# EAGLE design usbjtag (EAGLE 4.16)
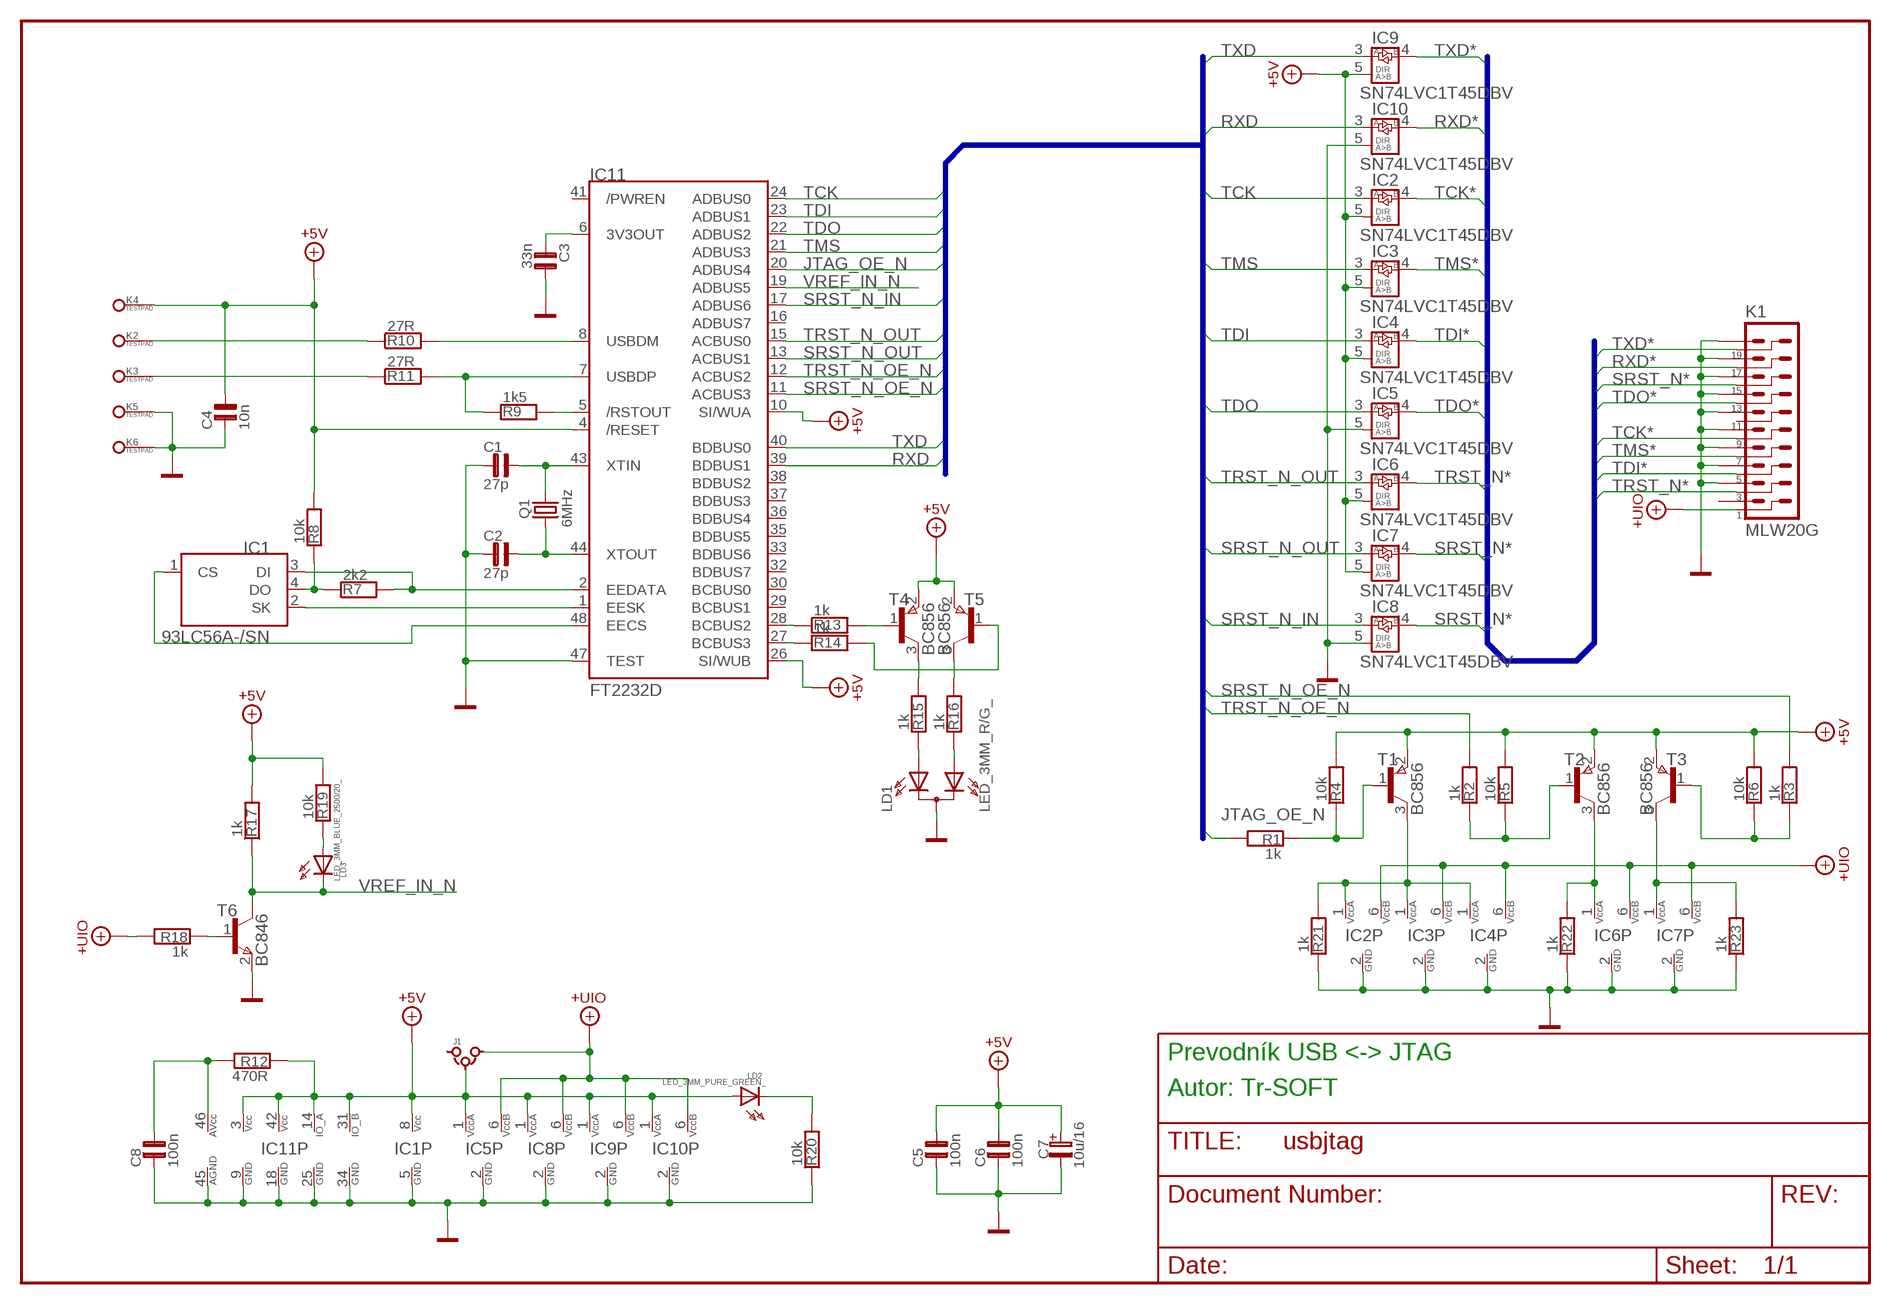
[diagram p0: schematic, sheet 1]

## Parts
C1  27p  C0805  [C0805]
C2  27p  C0805  [C0805]
C3  33n  C0805  [C0805]
C4  10n  C0805  [C0805]
C5  100n  C0805  [C0805]
C6  100n  C0805  [C0805]
C7  10u/16  CTANSMD-A  [CTANSMD-A]
C8  100n  C0805  [C0805]
IC1  93LC56A-/SN  [SO8]
IC2  SN74LVC1T45DBV  [SOT23-6]
IC3  SN74LVC1T45DBV  [SOT23-6]
IC4  SN74LVC1T45DBV  [SOT23-6]
IC5  SN74LVC1T45DBV  [SOT23-6]
IC6  SN74LVC1T45DBV  [SOT23-6]
IC7  SN74LVC1T45DBV  [SOT23-6]
IC8  SN74LVC1T45DBV  [SOT23-6]
IC9  SN74LVC1T45DBV  [SOT23-6]
IC10  SN74LVC1T45DBV  [SOT23-6]
IC11  FT2232D  [LQFP48]
J1  JUMPER_3  [S1G03J]
K1  MLW20G  MLW20G_  [MLW20G_]
K2  TESTPAD  [TESTPAD]
K3  TESTPAD  [TESTPAD]
K4  TESTPAD  [TESTPAD]
K5  TESTPAD  [TESTPAD]
K6  TESTPAD  [TESTPAD]
LD1  LED_3MM_R/G_  [LED_3MM_DUO_SMD]
LD2  LED_3MM_PURE_GREEN_  [LED_3MM_SMD]
LD3  LED_3MM_BLUE_2500/20_  [LED_3MM_SMD]
Q1  6MHz  Q-HC49/S  [Q-HC49/S]
R1  1k  R0805  [R0805]
R2  1k  R0805  [R0805]
R3  1k  R0805  [R0805]
R4  10k  R1206  [R1206]
R5  10k  R0805  [R0805]
R6  10k  R0805  [R0805]
R7  2k2  R0805  [R0805]
R8  10k  R0805  [R0805]
R9  1k5  R1206  [R1206]
R10  27R  R0805  [R0805]
R11  27R  R0805  [R0805]
R12  470R  R0805  [R0805]
R13  1k  R0805  [R0805]
R14  1k  R0805  [R0805]
R15  1k  R0805  [R0805]
R16  1k  R0805  [R0805]
R17  1k  R1206  [R1206]
R18  1k  R0805  [R0805]
R19  10k  R0805  [R0805]
R20  10k  R0805  [R0805]
R21  1k  R0805  [R0805]
R22  1k  R0805  [R0805]
R23  1k  R0805  [R0805]
T1  BC856  [SOT23]
T2  BC856  [SOT23]
T3  BC856  [SOT23]
T4  BC856  [SOT23]
T5  BC856  [SOT23]
T6  BC846  [SOT23]

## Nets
+5V: C4.2 C5.2 C6.2 C7.1(+) IC1.8(VCC) IC2.5(DIR) IC3.5(DIR) IC4.5(DIR) IC5.1(VCCA) IC6.5(DIR) IC7.5(DIR) IC8.1(VCCA) IC9.1(VCCA) IC9.5(DIR) IC10.1(VCCA) IC11.3(VCC) IC11.4(/RESET) IC11.10(SI/WUA) IC11.14(VCCIOA) IC11.26(SI/WUB) IC11.31(VCCIOB) IC11.42(VCC) J1.2(C) K4.1(P) LD2.A R4.2 R5.2 R6.2 R8.2 R12.1 R17.2 R19.2 T1.2(E) T2.2(E) T3.2(E) T4.2(E) T5.2(E)
+UIO: IC2.6(VCCB) IC3.6(VCCB) IC4.6(VCCB) IC5.6(VCCB) IC6.6(VCCB) IC7.6(VCCB) IC8.6(VCCB) IC9.6(VCCB) IC10.6(VCCB) J1.3 K1.1 R18.2
AVCC: C8.2 IC11.46(AVCC) R12.2
GND: C1.1 C2.1 C3.2 C4.1 C5.1 C6.1 C7.2(-) C8.1 IC1.5(GND) IC2.2(GND) IC3.2(GND) IC4.2(GND) IC5.2(GND) IC5.5(DIR) IC6.2(GND) IC7.2(GND) IC8.2(GND) IC8.5(DIR) IC9.2(GND) IC10.2(GND) IC10.5(DIR) IC11.9(GND) IC11.18(GND) IC11.25(GND) IC11.34(GND) IC11.45(AGND) IC11.47(TEST) K1.4 K1.6 K1.8 K1.10 K1.12 K1.14 K1.16 K1.18 K1.20 K5.1(P) K6.1(P) LD1.C(K) R20.1 R21.1 R22.1 R23.1 T6.2(E)
JTAG_OE: IC2.1(VCCA) IC3.1(VCCA) IC4.1(VCCA) R21.2 T1.3(C)
JTAG_OE_N: IC11.20(ADBUS4) R1.2
N$1: R1.1 R4.1 T1.1(B)
N$2: IC1.1(CS) IC11.48(EECS)
N$3: LD3.A R19.1
N$4: R18.1 T6.1(B)
N$5: IC1.2(SK) IC11.1(EESK)
N$6: R2.1 R5.1 T2.1(B)
N$7: R3.1 R6.1 T3.1(B)
N$8: IC1.3(DI) IC11.2(EEDATA) R7.2
N$9: IC1.4(DO) R7.1 R8.1
N$10: C1.2 IC11.43(XTIN) Q1.2
N$11: C2.2 IC11.44(XTOUT) Q1.1
N$12: LD2.C(K) R20.2
N$13: C3.1 IC11.6(3V3OUT)
N$14: IC11.5(/RSTOUT) R9.2
N$19: R15.2 T4.3(C)
N$20: R16.2 T5.3(C)
N$21: LD1.A2(AR) R15.1
N$22: LD1.A1(AG) R16.1
N$24: R13.2 T4.1(B)
N$25: R14.2 T5.1(B)
N$26: IC11.28(BCBUS2) R13.1
N$27: IC11.27(BCBUS3) R14.1
RXD: IC10.3(A) IC11.39(BDBUS1)
RXD*: IC10.4(B) K1.17
SRST_N*: IC7.4(B) IC8.4(B) K1.15
SRST_N_IN: IC8.3(A) IC11.17(ADBUS6)
SRST_N_OE_N: IC11.11(ACBUS3) R3.2
SRST_N_OUT: IC7.3(A) IC11.13(ACBUS1)
TCK: IC2.3(A) IC11.24(ADBUS0)
TCK*: IC2.4(B) K1.9
TDI: IC4.3(A) IC11.23(ADBUS1)
TDI*: IC4.4(B) K1.5
TDO: IC5.3(A) IC11.22(ADBUS2)
TDO*: IC5.4(B) K1.13
TMS: IC3.3(A) IC11.21(ADBUS3)
TMS*: IC3.4(B) K1.7
TRST_N*: IC6.4(B) K1.3
TRST_N_OE_N: IC11.12(ACBUS2) R2.2
TRST_N_OUT: IC6.3(A) IC11.15(ACBUS0)
TXD: IC9.3(A) IC11.40(BDBUS0)
TXD*: IC9.4(B) K1.19
USBDM: IC11.8(USBDM) R10.2
USBDM*: K2.1(P) R10.1
USBDP: IC11.7(USBDP) R9.1 R11.2
USBDP*: K3.1(P) R11.1
VCC_SRST: IC7.1(VCCA) R23.2 T3.3(C)
VCC_TRST: IC6.1(VCCA) R22.2 T2.3(C)
VREF_IN_N: IC11.19(ADBUS5) LD3.C(K) R17.1 T6.3(C)
Unconnected: IC11.16(ADBUS7) IC11.29(BCBUS1) IC11.30(BCBUS0) IC11.32(BDBUS7) IC11.33(BDBUS6) IC11.35(BDBUS5) IC11.36(BDBUS4) IC11.37(BDBUS3) IC11.38(BDBUS2) IC11.41(/PWREN) J1.1 K1.2 K1.11

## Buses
TRST_N*,TDI*,TMS*,TCK*,TDO*,SRST_N*,RXD*,TXD*
TCK,TMS,TDI,TDO,JTAG_OE_N,TRST_N_OE_N,TRST_N_OUT,SRST_N_OE_N,SRST_N_OUT,SRST_N_IN,RXD,TXD

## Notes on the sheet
- Prevodník USB <-> JTAG
- Autor: Tr-SOFT

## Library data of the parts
C1-C6 C8 = PASSIVE:C
C7 = PASSIVE:CTANSMD
IC1 = IO:93*56A-/?: Microwire 2kb ( 256B x 8 ) Serial EEPROM
IC2-IC10 = TTL74:SN74LVC1T45*
IC11 = IO:FT2232D
J1 = connectors:JUMPER_3
K1 = connectors:MLW20
K2-K6 = connectors:TESTPAD
LD1 = ACTIVE:LED_3MM_R/G
LD2 LD3 = ACTIVE:LED_3MM_*: Circle LED 3mm diamater.
Q1 = PASSIVE:Q-HC49
R1-R23 = PASSIVE:R
T1-T5 = ACTIVE:BC856
T6 = ACTIVE:BC846

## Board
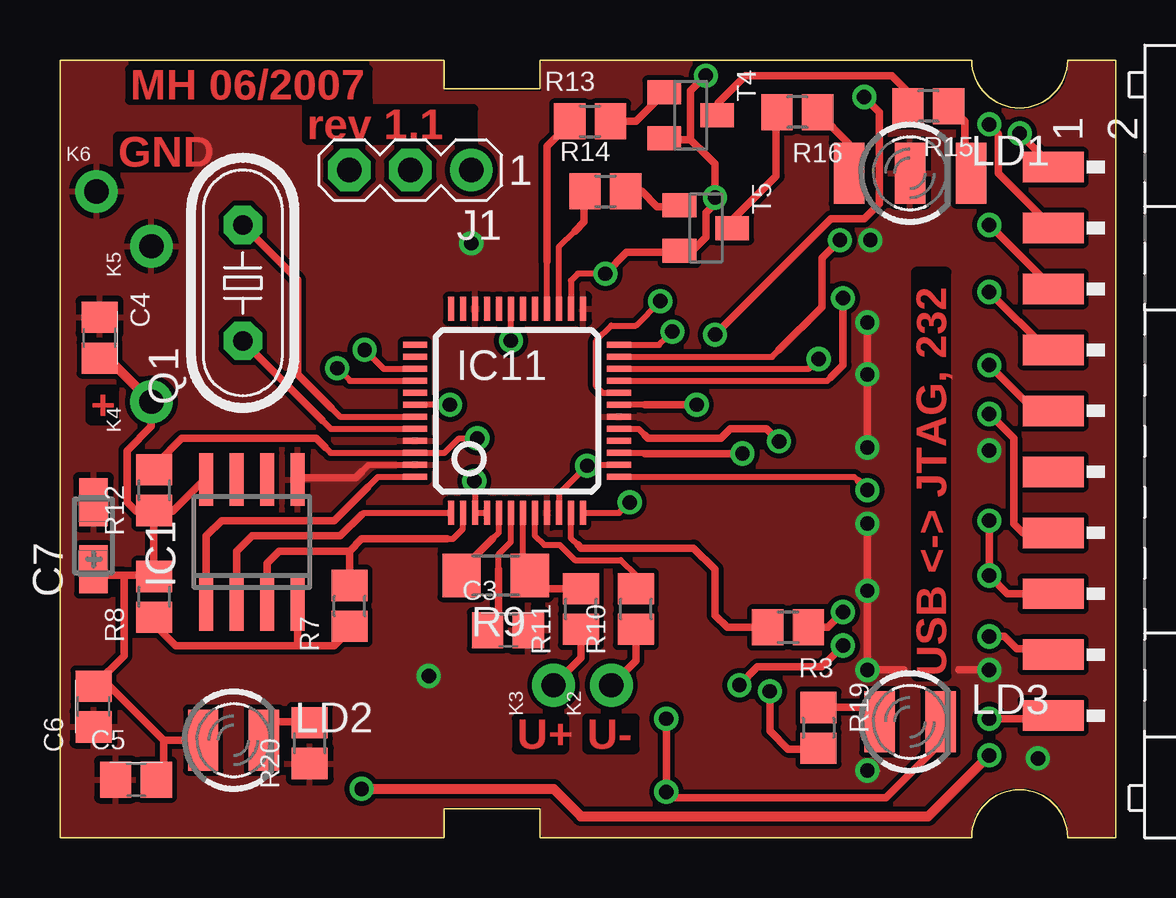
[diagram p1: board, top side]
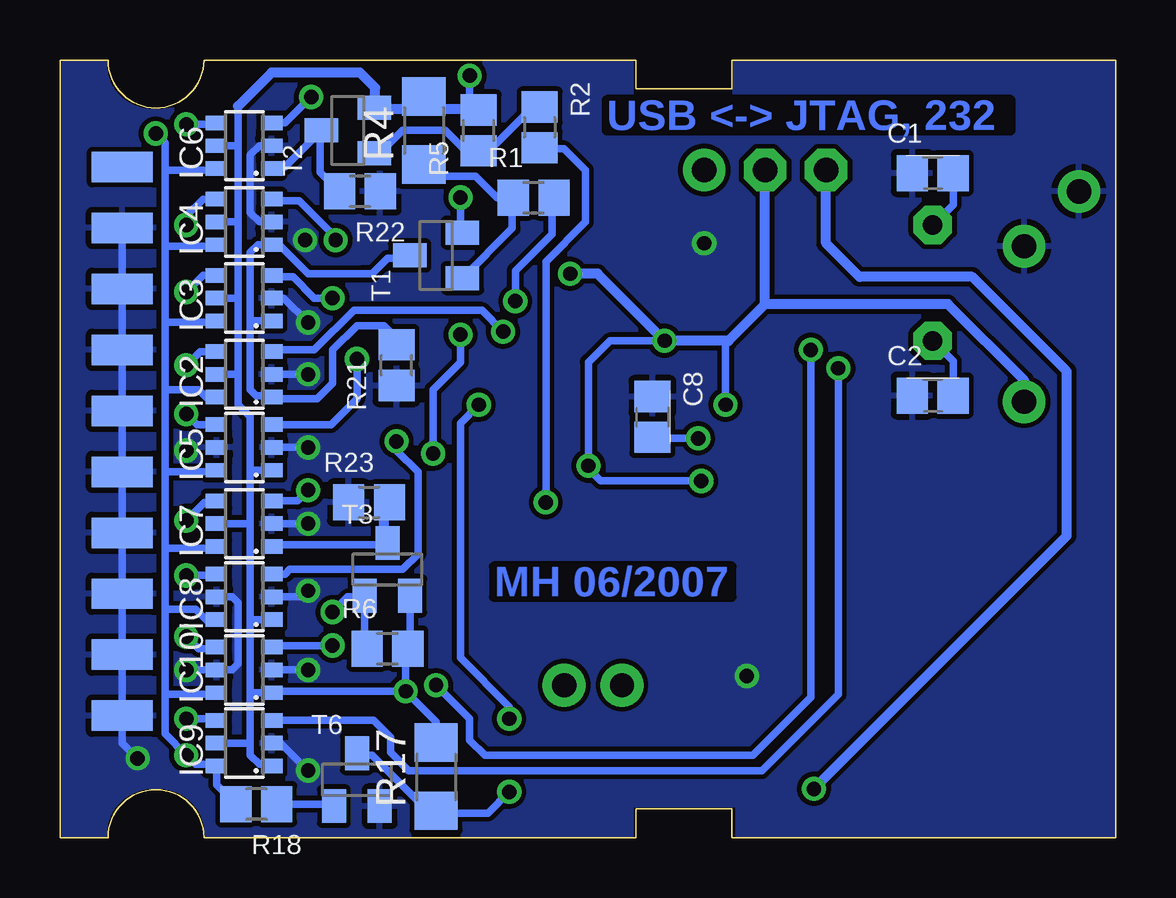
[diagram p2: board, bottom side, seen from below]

Size 44 x 32.4 mm. Coordinates in mm from the lower left corner, seen from the top.
Outline: 0,0 0,32.4 16,32.4 16,31.2 20,31.2 20,32.4 38,32.4 arc180 42,32.4 44,32.4 44,0 42,0 arc180 38,0 20,0 20,1.2 16,1.2 16,0 0,0
Copper layers (1*16): Top 0.035mm / dielectric 1.5mm / Bottom 0.035mm
Design rules "default": minimum track width 10mil, minimum drill 23mil, track to track 8mil, track to pad 8mil, pad to pad 8mil, via to via 8mil, smd to smd 8mil, copper to edge 0mil, drill to drill 8mil, minimum pad ring 10mil, minimum via ring 8mil, stop-mask expansion 4mil, vias tented up to drill 24mil, thermal gap 10mil

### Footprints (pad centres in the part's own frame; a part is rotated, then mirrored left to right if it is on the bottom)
C0805 = smd 1.3 x 1.5: 1 -0.85,0; 2 0.85,0
CTANSMD-A = smd 2 x 1.2: 1 -1.4,0; 2 1.4,0
SO8 = smd 0.6 x 2.2: 1 -1.905,-2.6; 2 -0.635,-2.6; 3 0.635,-2.6; 4 1.905,-2.6; 5 1.905,2.6; 6 0.635,2.6; 7 -0.635,2.6; 8 -1.905,2.6
SOT23-6 = smd 0.6 x 0.9: 1 -0.95,-1.15; 2 0,-1.15; 3 0.95,-1.15; 4 0.95,1.15; 5 0,1.15; 6 -0.95,1.15
LQFP48 = smd 0.26 x 1: 1 -2.75,-4.25; 2 -2.25,-4.25; 3 -1.75,-4.25; 4 -1.25,-4.25; 5 -0.75,-4.25; 6 -0.25,-4.25; 7 0.25,-4.25; 8 0.75,-4.25; 9 1.25,-4.25; 10 1.75,-4.25; 11 2.25,-4.25; 12 2.75,-4.25; 25 2.75,4.25; 26 2.25,4.25; 27 1.75,4.25; 28 1.25,4.25; 29 0.75,4.25; 30 0.25,4.25; 31 -0.25,4.25; 32 -0.75,4.25; 33 -1.25,4.25; 34 -1.75,4.25; 35 -2.25,4.25; 36 -2.75,4.25 | smd 1 x 0.26: 13 4.25,-2.75; 14 4.25,-2.25; 15 4.25,-1.75; 16 4.25,-1.25; 17 4.25,-0.75; 18 4.25,-0.25; 19 4.25,0.25; 20 4.25,0.75; 21 4.25,1.25; 22 4.25,1.75; 23 4.25,2.25; 24 4.25,2.75; 37 -4.25,2.75; 38 -4.25,2.25; 39 -4.25,1.75; 40 -4.25,1.25; 41 -4.25,0.75; 42 -4.25,0.25; 43 -4.25,-0.25; 44 -4.25,-0.75; 45 -4.25,-1.25; 46 -4.25,-1.75; 47 -4.25,-2.25; 48 -4.25,-2.75
S1G03J = drill 1.016 pad 1.778 round: 1 -2.54,0 | drill 1.016 pad 1.778 octagon: 2 0,0; 3 2.54,0
MLW20G_ = smd 1.27 x 2.54: 1 -11.43,-0.508; 3 -8.89,-0.508; 5 -6.35,-0.508; 7 -3.81,-0.508; 9 -1.27,-0.508; 11 1.27,-0.508; 13 3.81,-0.508; 15 6.35,-0.508; 17 8.89,-0.508; 19 11.43,-0.508 | smd 1.27 x 2.54 bottom: 2 -11.43,-0.508; 4 -8.89,-0.508; 6 -6.35,-0.508; 8 -3.81,-0.508; 10 -1.27,-0.508; 12 1.27,-0.508; 14 3.81,-0.508; 16 6.35,-0.508; 18 8.89,-0.508; 20 11.43,-0.508
TESTPAD = drill 1.016 pad 1.778 round: 1 0,0
LED_3MM_DUO_SMD = smd 1.27 x 2.54: A1 -2.54,0; A2 2.54,0; C 0,0
LED_3MM_SMD = smd 1.27 x 2.54: A -1.27,0; C 1.27,0
Q-HC49/S = drill 0.813 pad 1.6 octagon: 1 -2.413,0; 2 2.413,0
R0805 = smd 1.3 x 1.5: 1 -0.85,0; 2 0.85,0
R1206 = smd 1.6 x 1.803: 1 -1.422,0; 2 1.422,0
SOT23 = smd 1 x 1.4: 1 -0.95,-1.1; 2 0.95,-1.1; 3 0,1.1

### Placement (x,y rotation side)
C1  7.62,27.69 0 bottom
C2  7.62,18.41 0 bottom
C3  18.67,8.64 0 top
C4  1.65,20.83 270 top
C5  3.17,2.41 0 top
C6  1.4,5.46 90 top
C7  1.4,12.57 90 top
C8  19.3,17.53 270 bottom
IC1  8,12.32 0 top
IC2  36.32,19.3 90 bottom
IC3  36.32,22.48 90 bottom
IC4  36.32,25.65 90 bottom
IC5  36.32,16.26 90 bottom
IC6  36.32,28.83 90 bottom
IC7  36.32,13.08 90 bottom
IC8  36.32,10.03 90 bottom
IC9  36.32,3.94 90 bottom
IC10  36.32,6.99 90 bottom
IC11  19.05,17.78 0 top
J1  14.61,27.81 180 top
K1  41.91,16.51 270 top
K2  22.99,6.35 90 top
K3  20.57,6.35 90 top
K4  3.81,18.16 90 top
K5  3.81,24.64 90 top
K6  1.52,26.92 0 top
LD1  35.43,27.69 0 top
LD2  7.24,4.06 0 top
LD3  35.43,4.83 0 top
Q1  7.62,23.11 90 top
R1  24.26,26.67 0 bottom
R2  24,29.59 270 bottom
R3  30.35,8.76 180 top
R4  28.83,29.46 90 bottom
R5  26.54,29.46 90 bottom
R6  30.35,7.87 0 bottom
R7  12.06,9.65 90 top
R8  3.94,10.03 90 top
R9  18.16,10.92 180 top
R10  24,9.53 90 top
R11  21.72,9.53 90 top
R12  3.94,14.48 90 top
R13  22.1,29.84 0 top
R14  22.73,26.92 0 top
R15  36.2,30.48 180 top
R16  30.73,30.23 180 top
R17  28.32,2.54 90 bottom
R18  35.81,1.4 180 bottom
R19  31.62,4.57 270 top
R20  10.41,3.94 90 top
R21  29.97,19.68 90 bottom
R22  31.5,26.92 180 bottom
R23  31.11,13.97 0 bottom
T1  28.32,24.26 90 bottom
T2  32,29.46 90 bottom
T3  30.35,11.18 0 bottom
T4  26.29,30.1 270 top
T5  26.92,25.4 270 top
T6  31.62,2.41 0 bottom

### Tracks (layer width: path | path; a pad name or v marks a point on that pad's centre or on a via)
+5V  (via drill 0.6)
  Top 0.254: IC11.4 17.79,13.53 17.78,13.53 IC11.3 17.3,14.83 v17.27,14.86 | 18.8,20.83 IC11.31 | IC11.14 22.01,15.53 v21.97,15.49 20.8,14.32 IC11.10 | IC11.42 v16.25,18.03 v16.26,18.03 | IC11.26 21.3,23.2 21.59,23.5 v22.73,23.5
  Top 0.303: v29.59,6.1 29.59,4.45 30.35,3.68 31.62,3.68 R19.2 | 6.1,14.99 IC1.8 | 6.1,14.99 6.01,14.99 | 6.1,14.99 4.7,13.59 3.94,13.59 | K4.1 3.81,17.14 2.79,16.13 2.79,13.97 3.17,13.59 3.94,13.59 | 4.32,4.06 LD2.A | 4.32,4.06 2.03,6.35 1.44,6.35 | 1.44,6.35 C6.2 | C5.2 4.32,2.71 4.32,4.06 | v22.73,23.5 23.62,24.38 25.78,24.38 25.82,24.43 T5.2 26.36,24.45 26.92,25.02 | C7.1 1.4,10.92 2.67,10.92 | 3.9,10.92 R8.2 | 2.67,10.92 3.9,10.92 | 1.44,6.35 2.67,7.58 2.67,10.92 | v26.92,31.75 26.29,31.11 26.29,29.08 | T4.2 25.25,29.08 26.29,29.08 | 26.92,28.45 26.29,29.08 | 3.94,13.59 R12.1 | 3.9,10.92 3.9,13.55 3.94,13.59 | 18.8,20.83 v18.8,20.7
  Top 0.305: 26.92,25.02 26.92,26.04 27.3,26.42 v27.3,26.67 27.3,28.07 26.92,28.45
  Top 0.406: C4.2 1.99,19.98 K4.1
  Bottom 0.303: 36.58,28.83 IC6.5 | 36.58,22.48 36.58,19.3 | 36.58,25.65 36.58,22.48 | 36.58,28.83 36.58,25.65 | 36.58,25.65 IC4.5 | 36.58,22.48 IC3.5 | 36.58,19.3 IC2.5 | 36.58,19.3 36.58,18.03 36.07,17.53 36.07,15.37 | 36.07,15.37 36.07,13.08 | 36.07,3.94 36.07,3.43 35.69,3.05 35.18,3.05 35.17,3.04 IC9.1 | 36.07,6.1 36.07,3.94 | 36.07,9.14 36.07,6.1 | 36.07,13.08 36.07,9.14 | 36.07,3.94 IC9.5 | 36.07,6.1 36.01,6.04 IC10.1 35.18,6.1 v29.59,6.1 | IC8.1 36.01,9.08 36.07,9.14 | 36.07,13.08 IC7.5 | IC5.1 36.01,15.31 36.07,15.37 | 36.58,30.48 36.58,28.83 | R5.2 26.84,30.31 | 29.59,7.87 R6.2 | T3.2 29.4,8.06 29.59,7.87 | R5.2 26.54,30.35 | v29.59,6.1 29.59,7.87 | R17.2 28.32,4.83 v29.59,6.1 | v17.27,14.86 21.46,14.86 21.97,15.37 v21.97,15.49 21.97,19.81 21.08,20.7 v18.8,20.7 | v16.26,18.03 v16.25,18.04 16.26,18.04 16.26,20.7 | R5.2 26.58,30.35 26.92,30.35 v26.92,31.75
  Bottom 0.305: T1.2 27.3,25.29 v27.3,26.67
  Bottom 0.406: 36.58,30.48 35.18,31.88 31.5,31.88 30.86,31.24 30.86,30.35 | v22.73,23.5 21.59,23.5 v18.8,20.7 16.26,20.7 16.13,20.7 14.61,22.23 | K4.1 3.81,19.05 6.99,22.23 14.61,22.23 | 14.61,22.23 J1.2 | 30.96,30.35 30.99,30.35 | 30.96,30.35 T2.2 30.86,30.37 30.86,30.35 | 30.86,30.35 29.36,30.35 R4.2 28.83,30.35 26.54,30.35 | 30.86,30.35 30.96,30.35
+UIO  (via drill 0.6)
  Top 0.303: v40.01,29.34 K1.1
  Top 0.406: v38.73,3.43 36.2,0.89 21.72,0.89 20.57,2.03 v12.57,2.03
  Bottom 0.303: 39.62,24.64 39.62,27.81 | 39.62,21.46 39.62,24.64 | 39.62,18.67 39.62,21.46 | 39.62,15.24 39.62,18.67 | 39.62,12.06 39.62,15.24 | 39.62,5.97 39.62,4.32 v38.73,3.43 38.35,3.05 37.47,3.05 37.47,3.04 IC9.6 37.47,2.2 R18.2 | 39.62,5.97 39.62,9.53 | 39.62,9.53 39.62,12.06 | IC4.6 37.54,24.64 39.62,24.64 | IC3.6 37.54,21.46 39.62,21.46 | IC2.6 37.54,18.29 37.85,18.29 38.23,18.67 39.62,18.67 | IC5.6 37.54,15.24 39.62,15.24 | IC7.6 37.54,12.06 39.62,12.06 | IC8.6 37.54,9.02 37.85,9.02 38.35,9.53 39.62,9.53 | IC10.6 37.54,5.97 39.62,5.97 | v40.01,29.34 39.62,28.96 39.62,27.81 | IC6.6 37.54,27.81 39.62,27.81
  Bottom 0.406: v12.57,2.03 2.03,12.57 2.03,19.43 5.97,23.37 10.67,23.37 12.06,24.77 J1.3
AVCC  (via drill 0.6)
  Top 0.254: 11.05,16.26 11.28,16.03 IC11.46 16.03,16.03 16.64,16.64 v17.4,16.64
  Top 0.303: 11.05,16.26 10.67,16.64 5.08,16.64 4.06,15.62 4.06,15.37 3.98,15.37 R12.2
  Bottom 0.303: C8.2 19.3,16.64 v17.4,16.64
GND  (via drill 0.6)
  Top 0.254: IC11.47 12.86,15.53 12.57,15.24
  Top 0.303: v33.66,13.08 v33.66,10.29 v33.66,6.99 IC10.2 | v33.66,16.26 v33.66,19.3 v33.66,21.46 | v33.66,2.79 34.04,2.79 | v38.73,6.99 IC10.5 | 12.57,15.24 12.32,14.99 9.91,14.99 IC1.5
  Bottom 0.303: IC4.2 35.69,25.65 36.07,26.04 36.07,28.45 35.69,28.83 IC6.2 | IC8.5 36.83,10.03 36.58,9.78 36.58,7.24 36.83,6.99 IC10.5 | IC10.5 | v33.66,21.46 34.67,22.48 IC3.2 | v33.66,19.3 IC2.2 | IC5.2 v33.66,16.26 | v33.66,13.08 IC7.2 | v33.66,10.29 33.91,10.03 IC8.2 | IC10.2 v33.66,6.99 | IC9.2 34.8,3.94 v33.66,2.79 | IC10.5 v38.73,6.99 | K1.4 K1.6 K1.8 K1.10 K1.12 K1.14 K1.16 K1.18 K1.20 41.4,3.94 v40.77,3.3
  other vias: 33.78,24.89 38.73,16.13 15.37,6.73 17.14,24.77
  pour Top: 0.25,32.26 15.88,32.26 15.88,30.99 20.19,30.99 20.19,32.26 37.85,32.26 arc90 39.88,30.23 40.01,30.23 40.13,30.23 arc90 42.16,32.26 43.81,32.26 43.81,29.97 43.81,26.8 43.81,19.81 43.81,15.11 43.81,8.13 43.81,0.13 42.16,0.13 arc90 40.13,2.16 40.01,2.16 39.88,2.16 arc90 37.85,0.13 20.19,0.13 20.19,1.4 15.88,1.4 15.88,0.13 0.13,0.13 0.13,3.3 0.13,9.53 0.13,17.14 0.13,25.53 0.13,32.26
  pour Bottom: 0.13,32.26 15.88,32.26 15.88,30.99 20.19,30.99 20.19,32.26 37.72,32.26 37.85,32.26 arc90 39.88,30.23 40.01,30.23 40.13,30.23 arc90 42.16,32.26 43.81,32.26 43.81,26.16 43.81,16.38 43.81,10.29 43.81,0.13 42.16,0.13 arc90 40.13,2.16 40.01,2.16 39.88,2.16 arc90 37.85,0.13 20.19,0.13 20.19,1.4 15.75,1.4 15.75,0.13 0.13,0.13 0.13,8.26 0.13,20.95
JTAG_OE
  Bottom 0.303: 36.07,21.59 36.07,18.67 35.81,18.41 35.18,18.41 35.17,18.41 IC2.1 | 36.07,21.59 36.07,24.38 35.75,24.7 IC4.1 35.17,24.64 35.18,24.64 34.8,24.64 33.66,23.5 31.37,23.5 | IC3.1 36.01,21.53 36.07,21.59
  Bottom 0.305: T1.3 29.55,24.13 30.35,24.13 30.99,23.5 31.37,23.5 | R21.2 29.97,20.83 30.48,21.34 31.62,21.34 32.64,20.32 32.64,18.92 33.27,18.29 35.18,18.29 35.17,18.3 IC2.1
JTAG_OE_N  (via drill 0.6)
  Top 0.254: IC11.20 22.62,18.53 22.35,18.8 22.35,20.7 22.99,21.34 24,21.34 v25.02,22.35
  Bottom 0.305: v25.02,22.35 25.02,23.62 23.5,25.15 23.5,26.67 R1.2
N$1
  Bottom 0.305: 25.15,26.67 25.78,26.67 26.67,27.56 28.32,27.56 28.83,28.07 R4.1 | 25.15,26.67 R1.1 | T1.1 25.15,25.38 25.15,26.67
N$2
  Top 0.254: IC11.48 13.25,15.03 12.83,14.61
  Top 0.303: IC1.1 6.1,12.57 6.73,13.21 11.43,13.21 12.83,14.61
N$3
  Top 0.303: LD3.A 34.16,5.21 33.95,5.42 R19.1
N$4
  Bottom 0.303: T6.1 32.51,1.37 32.51,1.4 R18.1
N$5
  Top 0.254: IC11.1 12.64,13.53 12.57,13.46
  Top 0.303: IC1.2 7.37,11.94 8,12.57 11.68,12.57 12.57,13.46
N$6
  Bottom 0.303: 30.97,28.45 30.99,28.45 | 30.97,28.45 T2.1 | 30.97,28.45 30.73,28.45 29.72,29.46 27.94,29.46
  Bottom 0.305: 27.94,29.46 27.05,28.57 26.54,28.57 R5.1 26.54,28.7 26.04,28.7 24.26,30.48 24,30.48 R2.1
N$7  (via drill 0.6)
  Top 0.303: R3.1 31.24,8.8 31.24,8.76 32,8.76 v32.64,9.4
  Bottom 0.303: R6.1 31.24,7.87 31.3,7.93 | 31.3,7.93 T3.1 31.26,10.03 | 31.3,7.93 31.36,7.87 | 31.26,10.03 31.24,10.03 | v32.64,9.4 32,10.03 31.26,10.03
N$8
  Top 0.254: 16.13,12.45 16.38,12.45 16.8,12.86 IC11.2
  Top 0.303: 12.06,11.94 9.14,11.94 8.64,11.43 IC1.3 | 12.06,11.94 12.57,12.45 16.13,12.45 | 12.06,11.94 R7.2
N$9
  Top 0.303: 9.91,8 4.83,8 3.94,8.89 R8.1 | 9.91,8 11.43,8 12.06,8.64 R7.1 | 9.91,8 IC1.4
N$10
  Top 0.254: IC11.43 11.68,17.53 11.3,17.91
  Top 0.303: 11.3,17.91 9.91,19.3 9.91,23.24 Q1.2
  Bottom 0.303: C1.2 6.77,26.38 Q1.2
N$11
  Top 0.254: IC11.44 11.29,17.03 10.92,17.4
  Top 0.303: Q1.1 8.47,19.85 10.92,17.4
  Bottom 0.303: C2.2 6.77,19.85 Q1.1
N$12
  Top 0.303: R20.2 10.41,4.83 8.51,4.83 LD2.C
N$13
  Top 0.254: IC11.6 18.8,12.32 18.29,11.81 18.29,11.18
  Top 0.303: 18.29,11.18 18.29,9.14 17.91,8.76 17.78,8.76 17.78,8.68 C3.1
N$14
  Top 0.254: IC11.5 18.3,12.71 18.03,12.45
  Top 0.303: R9.2 16.74,11.15 18.03,12.45
N$19
  Top 0.303: R15.2 35.31,30.48 35.31,31.11 34.67,31.75 28.57,31.75 27.43,30.61 27.43,30.1 T4.3
N$20
  Top 0.303: T5.3 28.07,25.4 28.02,25.44 | 29.84,30.23 R16.2
  Top 0.305: 29.84,30.23 29.84,27.56 28.07,25.78 28.07,25.44 T5.3
N$21
  Top 0.303: R15.1 37.08,30.48 37.72,29.84 37.72,27.69 LD1.A2
N$22
  Top 0.303: R16.1 32.89,28.92 LD1.A1
N$24
  Top 0.303: 25.15,31.11 25.15,31.09 T4.1 25.19,31.03 24,29.84 R13.2
N$25
  Top 0.303: T5.1 25.82,26.33 25.78,26.29 24.89,26.29 24.26,26.92 R14.2
N$26
  Top 0.254: IC11.28 20.3,24.02
  Top 0.303: 20.3,24.02 20.3,28.81 21.34,29.84 R13.1
N$27
  Top 0.254: IC11.27 20.8,24.61 21.46,25.27
  Top 0.303: 21.46,25.27 21.84,25.65 21.84,26.92 R14.1
RXD  (via drill 0.6)
  Top 0.254: IC11.39 13.49,19.53 v12.7,20.32
  Top 0.303: v32.64,8 31.75,7.11 29.08,7.11 v28.32,6.35
  Bottom 0.303: IC10.3 35.11,8 v32.64,8 | v28.32,6.35 26.92,4.95 26.92,4.06 26.29,3.43 15.11,3.43 12.7,5.84 v12.7,20.32
RXD*  (via drill 0.6)
  Top 0.303: K1.17 41.15,7.87 39.88,7.87 39.37,8.38 v38.73,8.38
  Bottom 0.303: IC10.4 37.53,7.87 38.23,7.87 v38.73,8.38
SRST_N*  (via drill 0.6)
  Top 0.303: K1.15 39.5,10.16 v38.73,10.92 v38.73,13.21
  Bottom 0.303: 37.28,10.98 IC8.4 37.53,10.92 v38.73,10.92 | IC7.4 37.53,13.97 37.97,13.97 v38.73,13.21
SRST_N_IN  (via drill 0.6)
  Top 0.254: IC11.17 24.12,17.03 24.38,16.76
  Top 0.303: v29.97,16.51 29.45,17.03 27.95,17.03 27.56,16.64 24.51,16.64 24.38,16.76
  Bottom 0.303: IC8.3 34.61,10.98 34.42,11.18 29.72,11.18 29.08,11.81 29.08,15.24 29.97,16.13 v29.97,16.51
SRST_N_OE_N
  Top 0.254: IC11.11 21.3,12.48 21.59,12.19
  Top 0.303: R3.2 27.81,8.76 27.3,9.27 27.3,11.18 26.42,12.06 21.72,12.06 21.59,12.19
SRST_N_OUT  (via drill 0.6)
  Top 0.254: IC11.13 33.1,15.03 33.27,14.86
  Top 0.303: 33.27,14.86 v33.66,14.48
  Bottom 0.303: IC7.3 34.1,14.03 v33.66,14.48
TCK  (via drill 0.6)
  Top 0.254: IC11.24 24.98,20.53 25.27,20.83
  Top 0.303: 25.27,20.83 v25.53,21.08
  Bottom 0.303: IC2.3 35.11,20.32 33.4,20.32 31.75,21.97 26.42,21.97 v25.53,21.08
TCK*  (via drill 0.6)
  Top 0.303: v38.73,19.68 40.64,17.78 K1.9
  Bottom 0.303: IC2.4 38.17,20.25 v38.73,19.68
TDI  (via drill 0.6)
  Top 0.254: IC11.23 29.68,20.03 29.97,20.32
  Top 0.303: 29.97,20.32 31.75,22.1 31.75,24.13 v32.51,24.89
  Bottom 0.303: IC4.3 35.11,26.54 34.04,26.54 32.51,25.02 v32.51,24.89
TDI*  (via drill 0.6)
  Top 0.303: v38.73,25.53 K1.5
  Bottom 0.303: IC4.4 38.04,26.6 38.73,25.91 v38.73,25.53
TDO  (via drill 0.6)
  Top 0.254: IC11.22 31.21,19.53 31.37,19.68
  Top 0.303: 31.37,19.68 v31.62,19.94
  Bottom 0.303: v31.62,19.94 31.62,18.29 32.7,17.21 IC5.3
TDO*  (via drill 0.6)
  Top 0.303: K1.13 40.13,12.7 39.75,13.08 39.75,16.64 v38.73,17.65
  Bottom 0.303: IC5.4 38.29,17.21 v38.73,17.65
TMS  (via drill 0.6)
  Top 0.254: IC11.21 31.98,19.03 32.13,19.18
  Top 0.303: 32.13,19.18 32.64,19.68 v32.64,22.48
  Bottom 0.303: IC3.3 35.11,23.37 34.29,23.37 33.4,22.48 v32.64,22.48
TMS*  (via drill 0.6)
  Top 0.303: K1.7 41.15,20.32 v38.73,22.73
  Bottom 0.303: IC3.4 38.04,23.43 v38.73,22.73
TRST_N*  (via drill 0.6)
  Top 0.303: v38.73,29.72 39.12,29.34 39.12,27.69 K1.3
  Bottom 0.303: IC6.4 37.53,29.72 v38.73,29.72
TRST_N_OE_N  (via drill 0.6)
  Top 0.254: IC11.12 23.31,13.53 v23.75,13.97
  Bottom 0.303: v23.75,13.97 23.75,23.37
  Bottom 0.305: 23.75,23.37 23.75,24 22.1,25.65 22.1,27.81 22.99,28.7 24,28.7 R2.2
TRST_N_OUT  (via drill 0.6)
  Top 0.254: IC11.15 24.36,16.03 24.38,16
  Top 0.303: v27.3,20.95 32.13,25.78 33.53,25.78 34.16,26.42 34.16,30.23 v33.53,30.86 | 24.38,16 v28.45,16
  Bottom 0.303: v28.45,16 28.45,18.67 27.3,19.81 v27.3,20.95 | IC6.3 34.61,29.78 v33.53,30.86
TXD  (via drill 0.6)
  Top 0.254: IC11.40 12.09,19.03 v11.56,19.56
  Bottom 0.303: IC9.3 30.92,4.89 30.23,4.19 30.23,3.56 29.46,2.79 14.73,2.79 11.56,5.97 v11.56,19.56
TXD*  (via drill 0.6)
  Top 0.303: K1.19 41.27,4.95 v38.73,4.95
  Bottom 0.303: IC9.4 37.54,4.95 v38.73,4.95
USBDM
  Top 0.254: IC11.8 19.8,12.59 20.19,12.19 20.83,12.19 21.46,11.56 23.37,11.56 24,10.92 R10.2
USBDM*
  Top 0.303: K2.1 24,7.37 R10.1
USBDP
  Top 0.254: R9.1 19.33,11.18 19.3,11.18 IC11.7
  Top 0.303: R9.1 19.56,10.92 20.11,10.38 R11.2
USBDP*
  Top 0.303: K3.1 21.72,7.49 R11.1
VCC_SRST
  Bottom 0.303: IC7.1 35.18,12.19 30.44,12.19 T3.3
  Bottom 0.406: R23.2 30.48,13.97 30.48,12.28 T3.3
VCC_TRST
  Bottom 0.303: IC6.1 35.18,27.94 34.63,27.94 T2.3
  Bottom 0.305: T2.3 33.15,29.46 33.15,27.73 R22.2
VREF_IN_N  (via drill 0.6)
  Top 0.254: IC11.19 24.38,18.03
  Top 0.303: v26.54,18.03 24.38,18.03 | v25.27,4.95 v25.27,1.91 25.53,1.65 34.42,1.65 36.7,3.94 LD3.C
  Bottom 0.303: T6.3 31.62,3.43 30.99,3.43 28.32,0.76 R17.1 28.3,1.12 28.19,1.02 26.16,1.02 v25.27,1.91 | v26.54,18.03 27.3,17.27 27.3,7.49 25.27,5.46 v25.27,4.95

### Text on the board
Top: MH 06/2007 | rev 1.1 | GND | + | USB <-> JTAG, 232 | U+ | U-
Bottom: USB <-> JTAG, 232 | MH 06/2007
